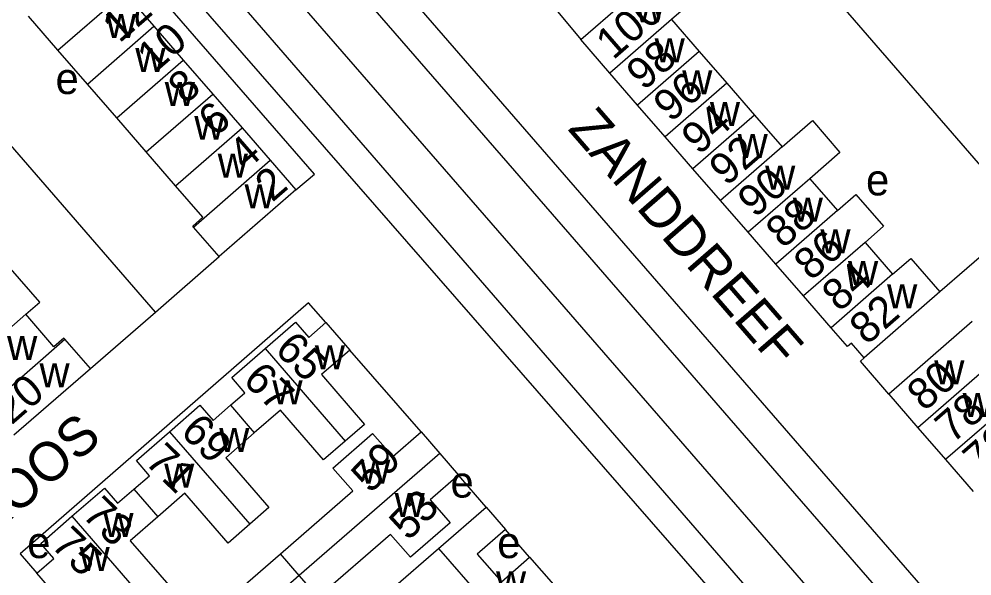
# Model space of a CAD drawing. Extents: x 155854 to 157362, y 383621 to 384685.
# Drawn here: x 156376.4 to 156498.5, y 384088.8 to 384160.1 of the extents above; entities that cross this region are included whole.
import ezdxf

# ---------------------------------------------------------------- set-up
doc = ezdxf.new("R2010")
doc.units = 0
for name, color, linetype in [('BLT_Basislijn', 7, 'Continuous'), ('BLT_Bebouwing', 7, 'Continuous'), ('BLT_Centroide', 7, 'Continuous'), ('BLT_Huisnummer', 7, 'Continuous'), ('BLT_Huisnummer_ tussenligend', 7, 'Continuous'), ('BLT_Onderverdeling_panden', 7, 'Continuous'), ('BLT_Straatnaam', 7, 'Continuous')]:
    doc.layers.add(name, color=color, linetype=linetype)

msp = doc.modelspace()

# ---------------------------------------------------------------- linework, layer by layer
at = {"layer": 'BLT_Basislijn'}
for p, q in [((156392.09, 384202.53), (156523.62, 384051.13)), ((156447.01, 384132.52), (156395.99, 384191.25)), ((156442.03, 384128.12), (156389.11, 384189.05)), ((156505.39, 384134.7), (156471.72, 384173.54)), ((156401.6, 384165.8), (156512.2, 384038.19)), ((156398.58, 384163.18), (156509.58, 384035.97)), ((156393.89, 384122.59), (156360.59, 384160.92)), ((156505.39, 384134.7), (156494.4, 384125.17)), ((156473.56, 384101.96), (156447.01, 384132.52)), ((156393.89, 384122.59), (156402.03, 384129.7)), ((156471.07, 384094.69), (156442.03, 384128.12)), ((156413.5, 384123.76), (156376.56, 384091.63)), ((156415.71, 384121.24), (156413.5, 384123.76)), ((156385.54, 384115.35), (156393.89, 384122.59)), ((156427.91, 384107.24), (156418.78, 384117.71)), ((156520.26, 384048.21), (156473.56, 384101.96)), ((156436.25, 384097.59), (156432.72, 384101.7)), ((156441.83, 384091.18), (156438.74, 384094.73)), ((156516.87, 384042.15), (156471.07, 384094.69)), ((156376.56, 384091.63), (156378.69, 384089.13))]:
    msp.add_line(p, q, dxfattribs=at)
for points in [[(156411.86, 384138.27), (156414.26, 384140.26), (156380.95, 384178.61)], [(156445.35, 384162.3), (156444.8, 384161.83), (156448.38, 384157.49)], [(156487.85, 384112.07), (156484.21, 384116.3), (156484.68, 384116.72)]]:
    msp.add_lwpolyline(points, dxfattribs=at)
at = {"layer": 'BLT_Bebouwing'}
for p, q in [((156389.92, 384163.55), (156393.68, 384159.21)), ((156381.39, 384156.15), (156377.62, 384160.49)), ((156460.03, 384160.06), (156463.57, 384155.98)), ((156393.68, 384159.21), (156397.45, 384154.86)), ((156385.16, 384151.8), (156381.39, 384156.15)), ((156463.57, 384155.98), (156467.11, 384151.9)), ((156397.45, 384154.86), (156401.22, 384150.52)), ((156388.93, 384147.46), (156385.16, 384151.8)), ((156467.11, 384151.9), (156470.65, 384147.82)), ((156401.22, 384150.52), (156404.99, 384146.18)), ((156392.7, 384143.12), (156388.93, 384147.46)), ((156470.65, 384147.82), (156474.19, 384143.74)), ((156404.99, 384146.18), (156408.58, 384142.04)), ((156396.47, 384138.78), (156392.7, 384143.12)), ((156408.58, 384142.04), (156411.86, 384138.27)), ((156477.73, 384139.67), (156481.27, 384135.59)), ((156411.86, 384138.27), (156402.03, 384129.7)), ((156484.81, 384131.51), (156488.35, 384127.43)), ((156380.61, 384118.44), (156377.26, 384122.31)), ((156415.71, 384121.24), (156418.78, 384117.71)), ((156498.55, 384121.38), (156487.85, 384112.07)), ((156375.73, 384106.85), (156385.54, 384115.35)), ((156427.91, 384107.24), (156430.32, 384104.48)), ((156430.32, 384104.48), (156432.72, 384101.7)), ((156430.17, 384092.31), (156436.25, 384097.59)), ((156436.25, 384097.59), (156438.74, 384094.73)), ((156424.06, 384087), (156430.17, 384092.31)), ((156441.83, 384091.18), (156444.87, 384087.69)), ((156381.78, 384085.6), (156378.69, 384089.13))]:
    msp.add_line(p, q, dxfattribs=at)
for points in [[(156448.38, 384157.49), (156459.05, 384166.76)], [(156459.05, 384166.76), (156462.78, 384162.45), (156460.03, 384160.06)], [(156452.12, 384153.19), (156448.38, 384157.49)], [(156455.66, 384149.11), (156452.12, 384153.19)], [(156459.21, 384145.04), (156455.66, 384149.11)], [(156474.19, 384143.74), (156478.06, 384147.12), (156481.6, 384143.05), (156477.73, 384139.67)], [(156462.75, 384140.96), (156459.21, 384145.04)], [(156466.29, 384136.89), (156462.75, 384140.96)], [(156399.97, 384134.74), (156396.47, 384138.78)], [(156481.27, 384135.59), (156483.63, 384137.66), (156487.18, 384133.58), (156484.81, 384131.51)], [(156469.83, 384132.81), (156466.29, 384136.89)], [(156398.75, 384133.47), (156398.65, 384133.6), (156399.97, 384134.74)], [(156402.03, 384129.7), (156398.75, 384133.47)], [(156473.38, 384128.74), (156469.83, 384132.81)], [(156476.92, 384124.66), (156473.38, 384128.74)], [(156488.35, 384127.43), (156490.68, 384129.46), (156494.4, 384125.17)], [(156377.26, 384122.31), (156379.06, 384123.88), (156375.31, 384128.17), (156373.52, 384126.61)], [(156494.4, 384125.17), (156484.68, 384116.72)], [(156480.46, 384120.58), (156476.92, 384124.66)], [(156407.92, 384117.91), (156411.81, 384121.29), (156413.53, 384119.33), (156415.71, 384121.24)], [(156483.06, 384118.62), (156482.55, 384118.18), (156480.46, 384120.58)], [(156382.27, 384119.12), (156382.15, 384119.25), (156380.87, 384118.14), (156380.61, 384118.44)], [(156385.54, 384115.35), (156382.27, 384119.12)], [(156403.48, 384110.65), (156405.34, 384112.27), (156403.65, 384114.21), (156407.92, 384117.91)], [(156484.68, 384116.72), (156483.06, 384118.62)], [(156418.78, 384117.71), (156415.14, 384114.58), (156420.68, 384108.21), (156418.2, 384106.06)], [(156487.85, 384112.07), (156491.59, 384107.76)], [(156395.69, 384107.27), (156399.58, 384110.66), (156401.26, 384108.72), (156403.48, 384110.65)], [(156418.2, 384106.06), (156415.43, 384103.65), (156409.89, 384110.02), (156406.55, 384107.12)], [(156391.13, 384099.91), (156393.12, 384101.63), (156391.44, 384103.58), (156395.69, 384107.27)], [(156406.55, 384107.12), (156402.88, 384103.93), (156408.42, 384097.56), (156405.97, 384095.43)], [(156409.9, 384091.61), (156419.19, 384099.68), (156416.62, 384102.62), (156421.71, 384107.04), (156424.28, 384104.09), (156427.91, 384107.24)], [(156491.59, 384107.76), (156495.13, 384103.69)], [(156495.13, 384103.69), (156498.68, 384099.61)], [(156432.72, 384101.7), (156429.08, 384098.54), (156431.64, 384095.59), (156426.56, 384091.18), (156424, 384094.12), (156414.72, 384086.06)], [(156383.18, 384096.43), (156387.34, 384100.04), (156389.03, 384098.1), (156391.13, 384099.91)], [(156405.97, 384095.43), (156403.18, 384093.01), (156397.65, 384099.38), (156394.2, 384096.38)], [(156378.69, 384089.13), (156380.86, 384091.02), (156379.18, 384092.96), (156383.18, 384096.43)], [(156394.2, 384096.38), (156390.65, 384093.3), (156396.19, 384086.93), (156393.48, 384084.58)], [(156438.74, 384094.73), (156435.12, 384091.59), (156438.21, 384088.04), (156441.83, 384091.18)], [(156390.89, 384075.11), (156394.56, 384078.26), (156391.98, 384081.23), (156397.07, 384085.64), (156399.63, 384082.69), (156409.9, 384091.61)]]:
    msp.add_lwpolyline(points, dxfattribs=at)
at = {"layer": 'BLT_Onderverdeling_panden'}
for p, q in [((156381.39, 384156.15), (156389.92, 384163.55)), ((156460.03, 384160.06), (156452.12, 384153.19)), ((156385.16, 384151.8), (156393.68, 384159.21)), ((156463.57, 384155.98), (156455.66, 384149.11)), ((156388.93, 384147.46), (156397.45, 384154.86)), ((156467.11, 384151.9), (156459.21, 384145.04)), ((156392.7, 384143.12), (156401.22, 384150.52)), ((156470.65, 384147.82), (156462.75, 384140.96)), ((156396.47, 384138.78), (156404.99, 384146.18)), ((156474.19, 384143.74), (156466.29, 384136.89)), ((156398.75, 384133.47), (156408.58, 384142.04)), ((156477.73, 384139.67), (156469.83, 384132.81)), ((156481.27, 384135.59), (156473.38, 384128.74)), ((156484.81, 384131.51), (156476.92, 384124.66)), ((156488.35, 384127.43), (156480.46, 384120.58)), ((156368.74, 384114.89), (156377.26, 384122.31)), ((156372.48, 384110.59), (156382.27, 384119.12)), ((156407.92, 384117.91), (156418.2, 384106.06)), ((156499.5, 384114.63), (156491.59, 384107.76)), ((156403.48, 384110.65), (156406.55, 384107.12)), ((156503.04, 384110.55), (156495.13, 384103.69)), ((156395.69, 384107.27), (156405.97, 384095.43)), ((156430.32, 384104.48), (156412.31, 384088.83)), ((156391.13, 384099.91), (156394.2, 384096.38)), ((156383.18, 384096.43), (156393.48, 384084.58)), ((156430.17, 384092.31), (156440.47, 384080.46)), ((156412.31, 384088.83), (156409.9, 384091.61)), ((156412.31, 384088.83), (156393.3, 384072.32)), ((156414.72, 384086.06), (156412.31, 384088.83))]:
    msp.add_line(p, q, dxfattribs=at)

# ---------------------------------------------------------------- texts
at = {"layer": 'BLT_Centroide'}
for s, p in [('w', (156455.3, 384159.72)), ('w', (156387.54, 384157.69)), ('w', (156457.85, 384154.59)), ('w', (156391.3, 384153.34)), ('e', (156381.08, 384150.52)), ('w', (156461.38, 384150.5)), ('w', (156395.07, 384149)), ('w', (156464.93, 384146.44)), ('w', (156398.85, 384144.66)), ('w', (156468.48, 384142.34)), ('w', (156401.86, 384139.81)), ('w', (156472.01, 384138.28)), ('e', (156484.94, 384137.54)), ('w', (156405.3, 384135.88)), ('w', (156475.55, 384134.19)), ('w', (156479.09, 384130.12)), ('w', (156482.63, 384126.06)), ('w', (156487.64, 384123.06)), ('w', (156374.87, 384116.44)), ('w', (156414.3, 384115.28)), ('w', (156379.02, 384112.97)), ('w', (156493.68, 384113.34)), ('w', (156408.87, 384110.78)), ('w', (156497.32, 384109.16)), ('w', (156402.05, 384104.67)), ('w', (156395, 384100.12)), ('w', (156420.11, 384100.62)), ('e', (156431.69, 384098.83)), ('w', (156424.53, 384096.36)), ('w', (156387.21, 384093.8)), ('e', (156377.45, 384091.08)), ('e', (156437.68, 384091.08)), ('w', (156384.15, 384089.41)), ('w', (156437.52, 384086.33))]:
    msp.add_text(s, height=4, dxfattribs=at).set_placement(p)
at = {"layer": 'BLT_Huisnummer'}
for s, rotation, p in [('100', 40.9826, (156452.53, 384154.8)), ('8', 40.9828, (156397.71, 384149.1)), ('94', 40.9826, (156463.5, 384142.6)), ('2', 40.9828, (156408.85, 384136.58)), ('90', 40.9826, (156470.7, 384134.55)), ('86', 40.9826, (156477.89, 384126.49)), ('82', 40.9826, (156485.03, 384118.26)), ('65', 315.9095, (156409.02, 384117.59)), ('80', 40.9888, (156492.4, 384109.76)), ('20', 40.9828, (156375.43, 384108.05)), ('69', 315.9095, (156396.93, 384107.08)), ('59', 45.9095, (156421.46, 384099.25)), ('53', 45.9095, (156426.32, 384093.18)), ('75', 315.9095, (156380.34, 384092.62))]:
    msp.add_text(s, height=4, rotation=rotation, dxfattribs=at).set_placement(p)
at = {"layer": 'BLT_Huisnummer_ tussenligend'}
for s, rotation, p in [('12', 40.9828, (156389.26, 384156.96)), ('10', 40.9828, (156393.73, 384153.08)), ('98', 40.9826, (156456.44, 384150.85)), ('96', 40.9826, (156459.9, 384146.79)), ('6', 40.9828, (156401.57, 384144.92)), ('4', 40.9828, (156405.44, 384140.59)), ('92', 40.9826, (156467.05, 384138.62)), ('88', 40.9826, (156474.3, 384130.62)), ('84', 40.9826, (156481.49, 384122.5)), ('67', 315.9095, (156404.93, 384113.69)), ('78', 40.9888, (156496, 384105.66)), ('76', 40.9888, (156499.58, 384101.55)), ('71', 315.9095, (156392.37, 384103.29)), ('73', 315.9095, (156384.32, 384096.48))]:
    msp.add_text(s, height=4, rotation=rotation, dxfattribs=at).set_placement(p)
at = {"layer": 'BLT_Straatnaam'}
for s, rotation, p in [('ZANDDREEF', 310.9827, (156446.61, 384146.01)), ('ZANDROOS', 40.9822, (156358.59, 384081.38))]:
    msp.add_text(s, height=5, rotation=rotation, dxfattribs=at).set_placement(p)

doc.saveas('drawing.dxf')
